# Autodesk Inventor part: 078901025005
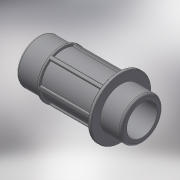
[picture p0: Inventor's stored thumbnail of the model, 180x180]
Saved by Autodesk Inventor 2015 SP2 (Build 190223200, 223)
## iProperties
Created: 2018-02
Part Number: 078901025005
Material: Generic
Description: PLASSON THREADED MALE ADAPTOR 25-1/2"
Document SubType Name: Modeling
Designer: KIM
Density: 1 g/cm^3
Appearance: Default
Author: KIM
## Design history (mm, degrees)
derived "078901.ipt"
feature "Solid1::078901.ipt"
tag "TaggingFeature1"
body "Solid1"
other parameters: "d4" = 1.04775, "d14" = 1.6764, "d15" = 0.8382, "d17" = 0, "d20" = 360 deg, "d40" = 17, "d41" = 20.955, "d45" = 23.0505, "d46" = 14.6685, "d47" = 1.7, "d77" = 79, "d78" = 25, "d85" = 0.20955, "d91" = 15.8, "d103" = 18.17, "d104" = 37, "d105" = 0.20955, "R_" = 20.955, "E_" = 37, "l_2" = 17, "l_" = 79, "d_" = 25
